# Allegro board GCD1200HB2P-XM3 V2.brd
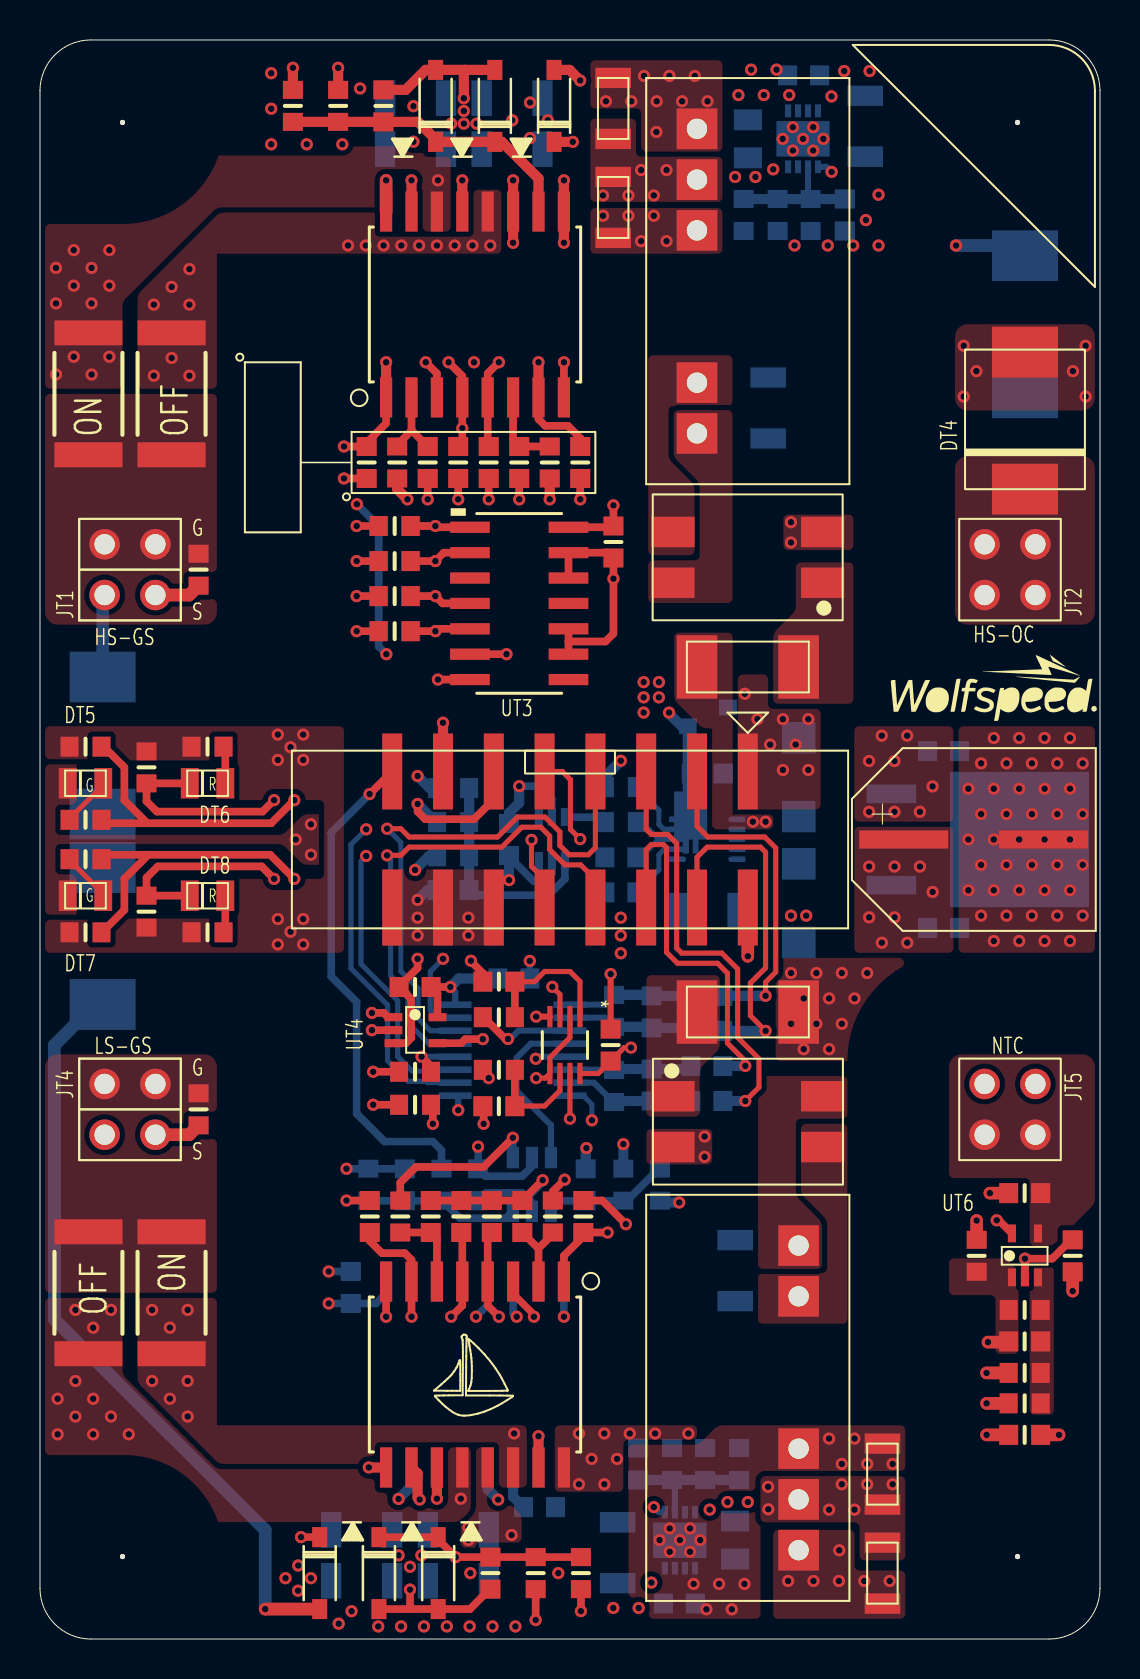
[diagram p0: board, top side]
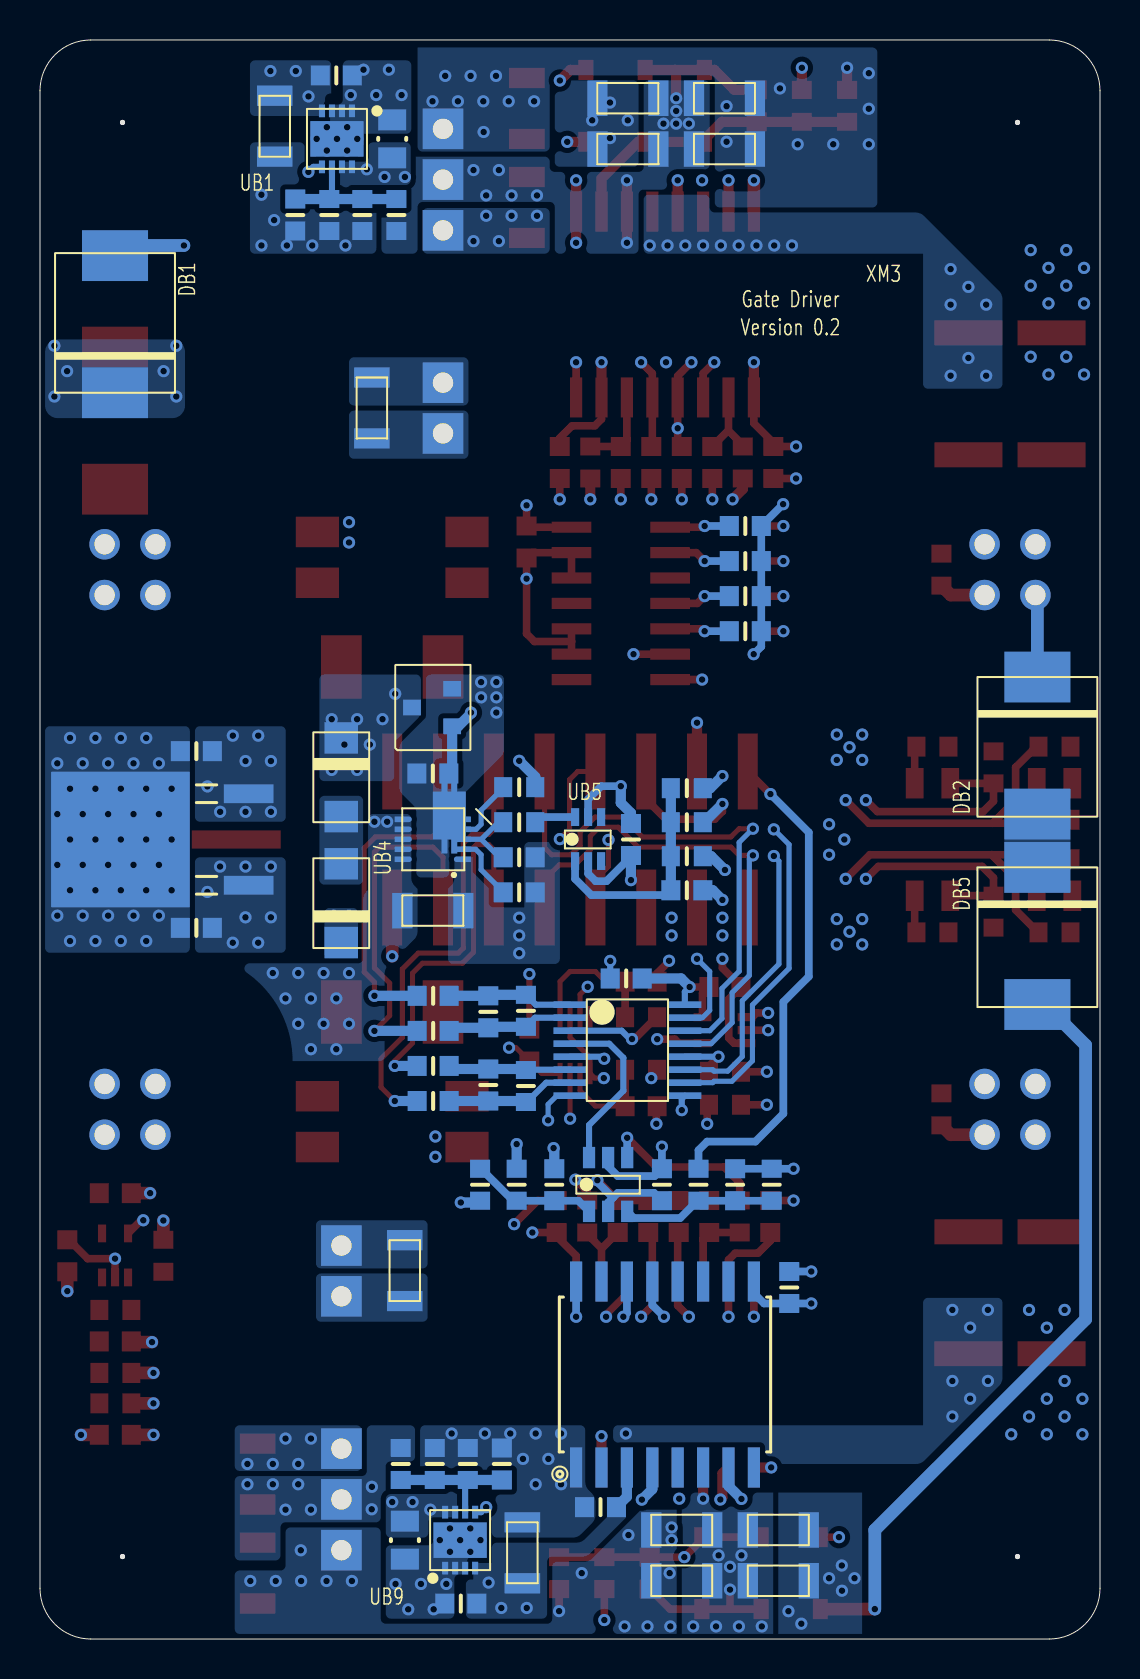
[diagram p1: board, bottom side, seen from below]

Outline 53 x 80 mm; copper layers: TOP, LAYER2, LAYER3, LAYER4, LAYER5, BOTTOM. Coordinates in mm from the lower left corner of the outline.
Outline path: 0,77.46 arc(0.74,79.26) 2.54,80 50.46,80 arc(52.26,79.26) 53,77.46 53,2.54 arc(52.26,0.74) 50.46,0 2.54,0 arc(0.74,0.74) 0,2.54 0,77.46

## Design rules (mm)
constraint set DEFAULT: min track width 0.254
net group FAULT: nets FAULT-OUTPUT-N FAULT-OUTPUT-P
net group HS-PWM: nets HS-PWM-N HS-PWM-P
net group LS-PWM: nets LS-PWM-N LS-PWM-P
net group RTD-OUTPUT: nets RTD-OUTPUT-N RTD-OUTPUT-P
net group HIGH_SIDE: nets HS-GATE N5948959 N6026555 N6026735 N6026739
net group HS_TO_VDC_DESAT_MIDPOINT: nets N6026743
net group LOW_SIDE: nets LS-GATE N5110224 N5949233 N6009828 N6009832 RTD1 RTD-ISO
net group PRIMARY: nets FAULT FLT_HS FLT_LS HS-PWM HS-PWM-INPUT LOGIC-ENABLE LS-PWM LS-PWM-INPUT N5110410 N5776744 N5776884 N5776892 N5776900 N5786131 N5786223 N5786329 N5786365 N5786573 N5786769 N5791884 N5791888 N5813663 N5829702 N5829738 N5829966 N5871306 N5927082 N5941912 N5941952 N6007380 N6007384 N6024502 N6026359 N6026535 N6032095 PS-DIS RDY_HS RDY_LS RESET RESET INPUT RTD-NON-ISO

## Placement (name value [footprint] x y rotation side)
CB1  2.2uF  [CAPC1608X90N]  38.18 78.23 180 bottom
CB2  10uF  [C_1206]  23.6 77.08 0 bottom
CB3  10uF  [C_1206]  18.78 77.08 0 bottom
CB4  10uF  [C_1206]  41.26 75.69 90 bottom
CB5  10uF  [C_1206]  23.6 74.54 0 bottom
CB6  10uF  [C_1206]  18.78 74.54 0 bottom
CB7  10000pF  [CAPC1608X90N]  40.24 71.24 90 bottom
CB8  10uF  [C_1206]  36.41 61.59 90 bottom
CB9  56 pF  [CAPC1608X90N]  17.74 55.68 180 bottom
CB10  56 pF  [CAPC1608X90N]  17.74 53.93 180 bottom
CB11  56 pF  [CAPC1608X90N]  17.74 52.18 180 bottom
CB12  56 pF  [CAPC1608X90N]  17.74 50.42 180 bottom
CB13  2.2uF  [CAPC1608X90N]  45.18 44.42 180 bottom
CB14  2.2uF  [CAPC1608X90N]  33.36 43.3 0 bottom
CB15  2.2uF  [CAPC1608X90N]  23.45 40 270 bottom
CB16  56 pF  [CAPC1608X90N]  29.04 39.11 180 bottom
CB17  10000pF  [CAPC1608X90N]  20.66 37.46 180 bottom
CB18  56 pF  [CAPC1608X90N]  29.04 37.36 180 bottom
CB19  10uF  [C_1206]  33.36 36.44 180 bottom
CB20  2.2uF  [CAPC1608X90N]  45.18 35.58 180 bottom
CB21  2.2uF  [CAPC1608X90N]  23.69 33.05 0 bottom
CB22  56 pF  [CAPC1608X90N]  30.59 31.38 90 bottom
CB23  56 pF  [CAPC1608X90N]  30.59 27.72 270 bottom
CB24  10000pF  [CAPC1608X90N]  27.29 22.73 90 bottom
CB25  2.2uF  [CAPC1608X90N]  21.9 22.73 270 bottom
CB26  56 pF  [CAPC1608X90N]  18.24 22.73 90 bottom
CB27  10uF  [C_1206]  34.76 18.43 270 bottom
CB28  2.2uF  [CAPC1608X90N]  15.54 17.59 90 bottom
CB29  10000pF  [CAPC1608X90N]  29.91 8.76 270 bottom
CB30  2.2uF  [CAPC1608X90N]  24.98 6.6 180 bottom
CB31  10uF  [C_1206]  20.91 5.46 180 bottom
CB32  10uF  [C_1206]  16.09 5.46 180 bottom
CB33  10uF  [C_1206]  28.88 4.31 270 bottom
CB34  10uF  [C_1206]  20.91 2.92 180 bottom
CB35  10uF  [C_1206]  16.09 2.92 180 bottom
CB36  2.2uF  [CAPC1608X90N]  31.96 1.77 0 bottom
CT1  56 pF  [CAPC1608X90N]  17.17 76.7 90 top
CT2  10uF  [C_1206]  28.66 76.58 270 top
CT3  10uF  [C_1206]  28.66 71.62 270 top
CT4  2.2uF  [CAPC1608X90N]  16.33 58.86 90 top
CT5  56 pF  [CAPC1608X90N]  19.38 58.86 270 top
CT6  56 pF  [CAPC1608X90N]  20.91 58.86 270 top
CT7  56 pF  [CAPC1608X90N]  22.44 58.86 270 top
CT8  56 pF  [CAPC1608X90N]  23.96 58.86 270 top
CT9  2.2uF  [CAPC1608X90N]  27.01 58.86 270 top
CT10  2.2uF  [CAPC1608X90N]  28.67 54.88 270 top
CT11  100uF  [ALUMELEC_8MMX10_5MM]  46.69 40 0 top
CT12  56 pF  [CAPC1608X90N]  22.94 32.89 180 top
CT13  2.2uF  [CAPC1608X90N]  18.75 32.62 180 top
CT14  2.2uF  [CAPC1608X90N]  28.53 29.72 90 top
CT15  56 pF  [CAPC1608X90N]  22.94 26.66 180 top
CT16  10000pF  [CAPC1608X90N]  49.23 22.31 180 top
CT17  2.2uF  [CAPC1608X90N]  16.49 21.14 90 top
CT18  56 pF  [CAPC1608X90N]  19.54 21.14 90 top
CT19  56 pF  [CAPC1608X90N]  21.06 21.14 90 top
CT20  56 pF  [CAPC1608X90N]  22.59 21.14 90 top
CT21  56 pF  [CAPC1608X90N]  24.12 21.14 90 top
CT22  2.2uF  [CAPC1608X90N]  27.17 21.14 270 top
CT23  2.2uF  [CAPC1608X90N]  51.63 19.17 270 top
CT24  56 pF  [CAPC1608X90N]  49.23 14.89 180 top
CT25  2.2uF  [CAPC1608X90N]  49.23 10.21 180 top
CT26  10uF  [C_1206]  42.12 8.25 90 top
CT27  56 pF  [CAPC1608X90N]  22.52 3.3 270 top
CT28  10uF  [C_1206]  42.12 3.3 90 top
DB1  US3M-13  [DO-214AB-SMC]  49.25 62.35 90 bottom
DB2  US3M-13  [DO-214AB-SMC]  3.13 48.13 270 bottom
DB3  SMAJ5932B-TP  [DO-214AC]  37.94 43.11 90 bottom
DB4  STPS2150A  [DO-214AC]  37.94 36.81 270 bottom
DB5  US3M-13  [DO-214AB-SMC]  3.13 38.6 270 bottom
DT1  BAT42W-TP  [SOD123]  19.78 76.7 90 top
DT2  10 V  [SOD123]  22.74 76.7 90 top
DT3  5.1 V  [SOD123]  25.71 76.7 90 top
DT4  US3M-13  [DO-214AB-SMC]  49.25 57.53 90 top
DT5  LG R971-KN-1  [D_0805]  2.27 42.82 180 top
DT6  LH R974-LP-1  [D_0805]  8.38 42.82 180 top
DT7  LG R971-KN-1  [D_0805]  2.27 37.18 180 top
DT8  LH R974-LP-1  [D_0805]  8.38 37.18 180 top
DT9  5.1 V  [SOD123]  13.99 3.3 270 top
DT10  10 V  [SOD123]  16.95 3.3 270 top
DT11  BAT42W-TP  [SOD123]  19.91 3.3 270 top
FT1  750 mA  [FUSE_SMD_SSQ2410]  35.39 48.63 0 top
FT2  750 mA  [FUSE_SMD_SSQ2410]  35.39 31.37 180 top
JT1  ESQ-102-33-L-D  [CON_2X2_100MIL_TH]  3.23 54.77 0 top
JT2  ESQ-102-33-L-D  [CON_2X2_100MIL_TH]  47.23 54.77 0 top
JT3  CON 2x8 SM  [CON_2X8_SHROUDED_SM]  26.5 40 270 top
JT4  ESQ-102-33-L-D  [CON_2X2_100MIL_TH]  3.23 27.77 0 top
JT5  ESQ-102-33-L-D  [CON_2X2_100MIL_TH]  47.23 27.77 0 top
LB1  1 uH  [INDC1608X95N]  33.34 32.18 180 bottom
LB2  1 uH  [INDC1608X95N]  33.34 30.43 180 bottom
LB3  1 uH  [INDC1608X95N]  33.34 28.67 180 bottom
LB4  1 uH  [INDC1608X95N]  33.34 26.92 180 bottom
LT1  10uH  [SRF0905]  35.38 54.12 180 top
LT2  10uH  [SRF0905]  35.4 25.88 0 top
NOREF  -  []  6.77 0 90 top
NOREF#2  -  []  48.88 4.12 90 top
NOREF#3  -  []  49.23 46.6 0 top
NOREF#4  -  []  51.69 2.05 0 top
NOREF#5  -  [unnamed#2]  4.12 4.12 0 top
NOREF#6  -  [unnamed#2]  48.88 75.88 0 top
NOREF#7  -  [unnamed#2]  48.88 4.12 0 top
NOREF#8  -  []  19.47 10.99 0 top
NOREF#9  -  []  4.12 4.12 0 top
NOREF#10  -  []  0 71.68 0 top
NOREF#11  -  [unnamed#2]  4.12 75.88 0 top
RB1  0  [RESC2012X70N]  35.39 75.05 270 bottom
RB2  10k  [RESC1608X55N]  38.54 71.24 90 bottom
RB3  10k  [RESC1608X55N]  36.88 71.24 90 bottom
RB4  2.2k  [RESC1608X55N]  35.18 71.24 90 bottom
RB5  120  [RESC1608X55N]  29.04 42.62 0 bottom
RB6  10k  [RESC1608X55N]  20.66 42.57 180 bottom
RB7  120  [RESC1608X55N]  29.04 40.87 180 bottom
RB8  120  [RESC1608X55N]  20.66 40.87 180 bottom
RB9  10k  [RESC1608X55N]  20.66 39.16 0 bottom
RB10  120  [RESC1608X55N]  28.7 31.43 270 bottom
RB11  120  [RESC1608X55N]  28.7 27.67 90 bottom
RB12  10k  [RESC1608X55N]  31 22.73 270 bottom
RB13  120  [RESC1608X55N]  29.17 22.73 90 bottom
RB14  120  [RESC1608X55N]  20.07 22.73 90 bottom
RB15  10k  [RESC1608X55N]  16.41 22.73 270 bottom
RB16  2.2k  [RESC1608X55N]  34.96 8.76 270 bottom
RB17  10k  [RESC1608X55N]  33.26 8.76 270 bottom
RB18  10k  [RESC1608X55N]  31.61 8.76 270 bottom
RB19  0  [RESC2012X70N]  34.76 4.95 90 bottom
RT1  2.2k  [RESC1608X55N]  12.64 76.7 90 top
RT2  120  [RESC1608X55N]  14.91 76.7 90 top
RT3  1  [RESC6432X70N]  2.42 62.3 270 top
RT4  1  [RESC6432X70N]  6.58 62.3 270 top
RT5  120  [RESC1608X55N]  17.86 58.86 90 top
RT6  120  [RESC1608X55N]  25.49 58.86 90 top
RT7  120  [RESC1608X55N]  17.74 55.68 0 top
RT8  120  [RESC1608X55N]  17.74 53.93 0 top
RT9  10k  [RESC1608X55N]  7.93 53.5 270 top
RT10  120  [RESC1608X55N]  17.74 52.18 0 top
RT11  120  [RESC1608X55N]  17.74 50.42 0 top
RT12  120  [RESC1608X55N]  2.27 44.64 180 top
RT13  330  [RESC1608X55N]  8.38 44.64 180 top
RT14  10k  [RESC1608X55N]  5.33 43.61 270 top
RT15  330  [RESC1608X55N]  2.27 40.99 0 top
RT16  330  [RESC1608X55N]  2.27 39.01 0 top
RT17  10k  [RESC1608X55N]  5.33 36.39 90 top
RT18  120  [RESC1608X55N]  2.27 35.36 180 top
RT19  330  [RESC1608X55N]  8.38 35.36 180 top
RT20  120  [RESC1608X55N]  22.94 31.11 0 top
RT21  120  [RESC1608X55N]  22.94 28.48 0 top
RT22  10k  [RESC1608X55N]  18.75 28.38 0 top
RT23  10k  [RESC1608X55N]  18.75 26.73 0 top
RT24  10k  [RESC1608X55N]  7.93 26.5 270 top
RT25  120  [RESC1608X55N]  18.01 21.14 270 top
RT26  120  [RESC1608X55N]  25.64 21.14 270 top
RT27  2.2k  [RESC1608X55N]  46.83 19.17 90 top
RT28  1  [RESC6432X70N]  2.42 17.32 90 top
RT29  1  [RESC6432X70N]  6.58 17.32 90 top
RT30  10k  [RESC1608X55N]  49.23 16.46 180 top
RT31  10k  [RESC1608X55N]  49.23 13.31 180 top
RT32  10k  [RESC1608X55N]  49.23 11.79 0 top
RT33  120  [RESC1608X55N]  24.78 3.3 270 top
RT34  2.2k  [RESC1608X55N]  27.05 3.3 270 top
UB1  LT3015EDD#TRPBF  [8-WDFN_EXPOSED_PAD]  38.15 75.05 270 bottom
UB2  DMP3056L-7  [SOT_23_3]  35.26 48.99 270 bottom
UB3  MC7805BDTG  [DPAK-3]  48.98 40 90 bottom
UB4  MP5000ADQ-LF-P  [10-VFDFN-THERMAL-V3_NO_VIA]  32.31 39.01 0 bottom
UB5  NC7WZ16P6X  [SC70_6]  26.25 38.92 180 bottom
UB6  2/2  [TSSOP_16]  23.63 29.46 180 bottom
UB7  SN74LVC2G14DBVR  [SOT_23_6]  25.55 21.39 180 bottom
UB8  ISO7810DWR  [DW0016B_N]  21.75 13.23 90 bottom
UB9  LT3015EDD#TRPBF  [8-WDFN_EXPOSED_PAD]  31.99 4.95 90 bottom
UT1  MGJ2D121505SC  [MGJ2]  32.85 60.31 90 top
UT2  ADUM4135  [DW0016B_N]  21.75 66.77 90 top
UT3  AND_4_2x  [D14]  23.96 51.81 0 top
UT4  SN74LVC1G32DCKR  [SC70_5]  17.67 31.11 270 top
UT5  XOR2 2X  [US8_2P40X2P10]  26.25 29.72 270 top
UT6  TLV7011DCKT  [SC70_5]  48.6 18.09 0 top
UT7  ADUM4135  [DW0016B_N]  21.75 13.23 270 top
UT8  MGJ2D121505SC  [MGJ2]  37.93 19.69 270 top

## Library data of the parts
CB1-CB36 CT1-CT10 CT12-CT28 = CAP
CT11 = CAP_P
DB1 DB2 DB5 DT4 = DIODE_1
DB3 DT2 DT10 = DIODE_ZENER_3
DB4 = DIODE_SCHOTTKY_13
DT1 DT11 = DIODE_SCHOTTKY_11
DT3 DT9 = DIODE_ZENER_4
DT5-DT8 = LED
FT1 FT2 = FUSE
JT1 JT2 JT4 JT5 = CON_2x2_100mil
JT3 = CON16A_Corrected
LB1-LB4 = INDUCTOR
LT1 LT2 = CM choke - LPD3015_2
RB1-RB19 RT1-RT34 = RES
UB1 UB9 = LT3015
UB2 = MOSFET_P_GSD
UB3 = MC7805BDTG: User Part Number: TMP-1562; Tolerance: TOL
UB4 = MP5000A_5
UB5 = BUFFER_2X_6P
UB6 = SN65C1167
UB7 = SN74LVC2G04
UB8 = ISO7810DWR: User Part Number: TMP-1565; Tolerance: TOL
UT1 UT8 = MGJ2
UT2 UT7 = ADUM4135BRWZ: User Part Number: TMP-1586; Tolerance: TOL
UT3 = AND4_2X: User Part Number: TMP-1541; Tolerance: TOL
UT4 = SN74LVC1G32
UT5 = XOR2_2X: User Part Number: TMP-1551; Tolerance: TOL
UT6 = TLV7011DCKT

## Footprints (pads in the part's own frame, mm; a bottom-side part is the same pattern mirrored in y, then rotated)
8-WDFN_EXPOSED_PAD
  rect 0.635x0.305 smd: 1(-1.4,0.75) 2(-1.4,0.25) 3(-1.4,-0.25) 4(-1.4,-0.75) 5(1.4,-0.75) 6(1.4,-0.25) 7(1.4,0.25) 8(1.4,0.75)
  rect 1.778x2.667 smd: 9(0,0)
10-VFDFN-THERMAL-V3_NO_VIA
  custom 0.07x0.07 smd: 1(-0.43,0) 2(-0.43,-0.5) 3(-0.43,-1) 4(-0.43,-1.5) 5(-0.43,-2) 6(2.53,-2) 7(2.53,-1.5) 8(2.53,-1) 9(2.53,-0.5) 10(2.53,0)
  custom 0.412x0.412 smd: 11(0.225,-2.19)
ALUMELEC_8MMX10_5MM
  rect 4.445x0.914 smd: 1(-3.505,0) 2(3.48,0)
C_1206
  rect 1.016x1.778 smd: 1(-1.524,0) 2(1.524,0)
CAPC1608X90N
  rect 0.95x1 smd: 1(-0.8,0) 2(0.8,0)
CON_2X2_100MIL_TH
  round 1.524 hole 1.016: 1(0,0) 2(0,-2.54) 3(2.54,0) 4(2.54,-2.54)
CON_2X8_SHROUDED_SM
  rect 3.8x1 smd: 1(-3.404,8.89) 2(3.404,8.89) 3(-3.404,6.35) 4(3.404,6.35) 5(-3.404,3.81) 6(3.404,3.81) 7(-3.404,1.27) 8(3.404,1.27) 9(-3.404,-1.27) 10(3.404,-1.27) 11(-3.404,-3.81) 12(3.404,-3.81) 13(-3.404,-6.35) 14(3.404,-6.35) 15(-3.404,-8.89) 16(3.404,-8.89)
D14
  rect 1.981x0.559 smd: 1(-2.464,3.81) 2(-2.464,2.54) 3(-2.464,1.27) 4(-2.464,0) 5(-2.464,-1.27) 6(-2.464,-2.54) 7(-2.464,-3.81) 8(2.464,-3.81) 9(2.464,-2.54) 10(2.464,-1.27) 11(2.464,0) 12(2.464,1.27) 13(2.464,2.54) 14(2.464,3.81)
D_0805
  rect 0.889x1.524 smd: 1(-0.889,0) 2(0.889,0)
DO-214AB-SMC
  rect 2.54x3.302 smd: A(6.858,0) C(0,0)
DO-214AC
  rect 1.575x1.676 smd: A(-1.968,0) C(1.968,0)
DPAK-3
  rect 0.94x2.489 smd: 1(-2.29,-6.413) 3(2.29,-6.413)
  rect 6.782x6.934 smd: 2(0,0)
DW0016B_N
  rect 2.007x0.61 smd: 1(-4.65,4.445) 2(-4.65,3.175) 3(-4.65,1.905) 4(-4.65,0.635) 5(-4.65,-0.635) 6(-4.65,-1.905) 7(-4.65,-3.175) 8(-4.65,-4.445) 9(4.65,-4.445) 10(4.65,-3.175) 11(4.65,-1.905) 12(4.65,-0.635) 13(4.65,0.635) 14(4.65,1.905) 15(4.65,3.175) 16(4.65,4.445)
FUSE_SMD_SSQ2410
  rect 2.032x3.175 smd: 1(-2.54,0) 2(2.54,0)
INDC1608X95N
  rect 0.95x1 smd: 1(-0.8,0) 2(0.8,0)
MGJ2
  rect 2.032x2.032 hole 1.016: 1(0,0) 2(2.54,0) 5(10.16,0) 6(12.7,0) 7(15.24,0)
RESC1608X55N
  rect 0.9x1 smd: 1(-0.8,0) 2(0.8,0)
RESC2012X70N
  rect 1.05x1.4 smd: 1(-0.95,0) 2(0.95,0)
RESC6432X70N
  rect 1.25x3.4 smd: 1(-3.05,0) 2(3.05,0)
SC70_5
  rect 0.406x0.889 smd: 1(0,0) 2(0.65,0) 3(1.3,0) 4(1.3,2.2) 5(0,2.2)
SC70_6
  rect 0.406x0.889 smd: 1(0,0) 2(0.65,0) 3(1.3,0) 4(1.3,2.2) 5(0.65,2.2) 6(0,2.2)
SOD123
  rect 1x0.75 smd: A(1.8,0) C(-1.8,0)
SOT_23_3
  rect 0.787x0.889 smd: 1(3.327,2.87) 2(1.448,2.87) 3(2.388,0.864)
SOT_23_6
  rect 0.61x1.067 smd: 1(0,0) 2(0.953,0) 3(1.905,0) 4(1.905,2.692) 5(0.953,2.692) 6(0,2.692)
SRF0905
  rect 2.159x1.524 smd: 1(-3.747,1.27) 2(-3.747,-1.27) 3(3.734,-1.27) 4(3.734,1.27)
TSSOP_16
  rect 1.651x0.33 smd: 1(-2.87,2.276) 2(-2.87,1.626) 3(-2.87,0.975) 4(-2.87,0.325) 5(-2.87,-0.325) 6(-2.87,-0.975) 7(-2.87,-1.626) 8(-2.87,-2.276) 9(2.87,-2.276) 10(2.87,-1.626) 11(2.87,-0.975) 12(2.87,-0.325) 13(2.87,0.325) 14(2.87,0.975) 15(2.87,1.626) 16(2.87,2.276)
unnamed#2
  round 0.254 hole 4.445 unplated: (0,0)
US8_2P40X2P10
  rect 1.067x0.254 smd: 1(-1.422,0.75) 2(-1.422,0.25) 3(-1.422,-0.25) 4(-1.422,-0.75) 5(1.422,-0.75) 6(1.422,-0.25) 7(1.422,0.25) 8(1.422,0.75)

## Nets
5V: CB13.2 CB15.1 CB21.1 CB25.1 CB28.2 CT4.1 CT9.1 CT10.1 CT13.1 CT14.1 CT17.1 CT22.1 RB9.1 RB12.2 RT12.2 RT13.2 RT14.1 RT17.1 RT18.2 RT19.2 RT22.2 RT23.2 UB3.3(OUT) UB5.5(VCC) UB6.12 UB6.16(VCC) UB7.5 UB8.14(VCC2) UT2.7 UT3.14 UT4.5 UT5.8 UT7.7
12V: CB14.2 CB20.2 CT11.1 UB2.2(S) UB3.1 UB4.11(VCC)
12V_SWITCHED: CB19.1 FT1.1 FT2.1 RB5.1 UB4.6 UB4.7 UB4.8 UB4.9 UB4.10
-5V_HS: CB1.2 CT3.2 RB1.1 UB1.1 UB1.2 UB1.3(SHDN) UB1.9 UT1.5
-5V_LS: CB36.2 CT26.2 RB19.1 UB9.1 UB9.2 UB9.3(SHDN) UB9.9 UT8.5
0: CB9.2 CB10.2 CB11.2 CB12.2 CB13.1 CB14.1 CB15.2 CB16.2 CB17.2 CB18.2 CB19.2 CB20.1 CB21.2 CB24.2 CB25.2 CB26.2 CB28.1 CT4.2 CT5.2 CT6.2 CT7.2 CT8.2 CT9.2 CT10.2 CT11.2 CT12.2 CT13.2 CT14.2 CT15.2 CT17.2 CT18.2 CT19.2 CT20.2 CT21.2 CT22.2 DB4.C DT5.2(C) DT7.2(C) JT3.2 JT3.12 JT3.14 JT3.16 LT1.2 LT2.2 RB6.2 RB15.1 UB2.1 UB3.2 UB4.1 UB5.2 UB6.8 UB7.2 UB8.9 UB8.16 UT2.1 UT2.3 UT2.8 UT3.7 UT3.9 UT3.10 UT3.12 UT3.13 UT4.3 UT5.4 UT7.1 UT7.3 UT7.8
FAULT: UB6.15 UT3.6
FAULT-OUTPUT-N: JT3.8 UB6.13
FAULT-OUTPUT-P: JT3.7 UB6.14
FLT_HS: CT7.1 DT6.2(C) RT7.1 RT14.2 UT2.5
FLT_LS: CT19.1 DT8.2(C) RT8.1 RT17.2 UT7.5
HS-DRAIN: DT4.C(CATHODE) JT2.1 JT2.2 JT2.3 JT2.4
HS-GATE: JT1.1 JT1.3 RT3.2 RT4.2 RT9.1 UT2.15
HS-PWM: RT5.1 UT5.7
HS-PWM-INPUT: RT20.1 RT23.1 UB6.3 UT4.1
HS-PWM-N: JT3.4 LB2.1
HS-PWM-P: JT3.3 LB1.1
HS-SOURCE: CB1.1 CB2.1 CB3.2 CB4.2 CB5.1 CB6.2 CT1.2 CT2.2 CT3.1 DB2.C(CATHODE) DT1.A DT2.A JT1.2 JT1.4 RB4.1 RT9.2 UB1.4 UB1.5 UT1.6(COM) UT2.11
HS-VDD: CB3.1 CB6.1 CT2.1 RT1.2 UT1.7 UT2.13
HS-VSS: CB2.2 CB4.1 CB5.2 CB7.1 RB1.2 RB2.1 RB3.1 UB1.7 UB1.8 UT2.9 UT2.16(VSS2_1)
LOGIC-ENABLE: JT3.13 RB13.2
LS-GATE: JT4.1 JT4.3 RT24.1 RT28.2 RT29.2 UT7.15
LS-PWM: RT26.1 UT5.3(Y)
LS-PWM-INPUT: RT21.1 RT22.1 UB6.5 UT4.2
LS-PWM-N: JT3.6 LB3.1
LS-PWM-P: JT3.5 LB4.1
LS-SOURCE: CB30.2 CB31.2 CB32.1 CB33.2 CB34.2 CB35.1 CB36.1 CT23.2 CT25.2 CT26.1 CT27.2 CT28.2 DT10.A DT11.A JT4.2 JT4.4 RB16.1 RT24.2 RT32.1 UB8.3 UB9.4 UB9.5 UT6.5(VCC) UT7.11 UT8.6(COM)
LS-VDD: CB31.1 CB34.1 CT28.1 RT34.2 UT7.13 UT8.7
LS-VSS: CB29.1 CB30.1 CB32.2 CB33.1 CB35.2 CT16.2 CT23.1 CT25.1 RB17.1 RB18.1 RB19.2 RT31.2 UB8.1 UB8.7 UB9.7 UB9.8 UT6.2 UT7.9 UT7.16(VSS2_1)
NC2: UT3.3
NC_1: UB8.5
NC_2: UB8.6
NC_3: UB8.8
NC_4: UB8.10
NC_5: UB8.11
NC_6: UB8.12
NC_7: UB8.15
PS-DIS: JT3.11 RB8.2
RDY_HS: CT6.1 RT10.1 RT12.1 RT15.2 UT2.4
RDY_LS: CT20.1 RT11.1 RT16.2 RT18.1 UT7.4
RESET: RT6.1 RT25.1 UB7.4(2Y)
RESET INPUT: JT3.15 RB14.2
RTD1: JT5.1 JT5.3 RT27.2
RTD2: CT16.1 JT5.2 JT5.4 UT6.4
RTD-ISO: CT24.2 RT27.1 RT30.2 UB8.4 UT6.1
RTD-NON-ISO: UB6.9 UB8.13
RTD-OUTPUT-N: JT3.10 UB6.11
RTD-OUTPUT-P: JT3.9 UB6.10
UNPROTECTED_VIN: DB3.C JT3.1 UB2.3
VOUT_OFF_HS: RT4.1 UT2.12
VOUT_OFF_LS: RT28.1 UT7.12
VOUT_ON_HS: RT3.1 UT2.14
VOUT_ON_LS: RT29.1 UT7.14
N5110224: CT27.1 DT10.C DT11.C RT33.1 RT34.1 UT7.10
N5110410: CT21.1 RT26.2 UT7.2
N5143626: FT1.2 LT1.1
N5776744: RB5.2 UB4.4
N5776884: CB18.1 UB4.2
N5776892: CB17.1 RB6.1 RB8.1 RB9.2 UB5.1
N5776900: CB16.1 RB7.1 UB4.3
N5777665: CB8.1 LT1.4 UT1.1
N5777737: CB8.2 LT1.3 UT1.2
N5778706: CB27.1 LT2.4 UT8.1
N5778794: CB27.2 LT2.3 UT8.2
N5780153: FT2.2 LT2.1
N5786131: CB22.1 LB2.2 RB10.2 UB6.2
N5786223: CB22.2 LB1.2 RB10.1 UB6.1
N5786329: CB23.1 LB3.2 RB11.2 UB6.6
N5786365: CB23.2 LB4.2 RB11.1 UB6.7
N5786573: UB6.4 UB7.6
N5786769: CB24.1 RB12.1 RB13.1 UB7.1
N5791884: DT8.1 RT19.1
N5791888: DT6.1 RT13.1
N5813663: CB9.1 RT7.2 UT3.1
N5829702: CT12.1 RT20.2 UT5.1
N5829738: UT4.4(Y) UT5.2 UT5.5
N5829966: CT15.1 RT21.2 UT5.6
N5871306: CB11.1 RT10.2 UT3.4
N5927082: DB3.A DB4.A
N5941912: CB10.1 RT8.2 UT3.2
N5941952: CB12.1 RT11.2 UT3.5
N5948959: CB7.2 RB2.2 RB3.2 RB4.2 UB1.6
N5949233: CB29.2 RB16.2 RB17.2 RB18.2 UB9.6
N5961728: CT24.1 RT30.1 RT31.1 RT32.2 UT6.3
N6007380: DT7.1 RT16.1
N6007384: DT5.1 RT15.1
N6009828: DT9.C RT33.2
N6009832: DB5.A DT9.A
N6009836: DB2.A DB5.C(CATHODE)
N6024502: CB26.1 RB14.1 RB15.2 UB7.3
N6026359: CT5.1 RT5.2 UT2.2
N6026535: CT8.1 RT6.2 UT2.6
N6026555: CT1.1 DT1.C DT2.C RT1.1 RT2.1 UT2.10
N6026735: DT3.C RT2.2
N6026739: DB1.A DT3.A
N6026743: DB1.C(CATHODE) DT4.A
N6032095: CT18.1 RT25.2 UT7.6
N57768605: RB7.2 UB5.6

Pads without a net: UB4 5; UB5 3 4; UB8 2; UT3 8 11

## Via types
v1: diameter 0.61, hole 0.33, TOP to BOTTOM, 430 vias

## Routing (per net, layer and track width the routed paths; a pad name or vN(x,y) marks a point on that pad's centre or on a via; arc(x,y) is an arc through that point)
5V: length 46.2
  TOP w0.254: v1(29.55,29.59) 29.2,29.59 CT14.1 27.91,28.29 UT5.8
  TOP w0.381: v1(28.67,56.72) CT10.1 28.61,55.62 UT3.14 ; CT9.1 27.01,60.08 26.4,60.7 25.26,60.7 24.93,61.03 UT2.7 ; v1(29.29,20.75) 28.11,21.94 CT22.1 ; v1(19.08,29.13) 19.55,28.66 RT22.2 ; RT23.2 19.64,26.64 v1(19.64,25.78) ; CT17.1 16.49,19.92 17.1,19.3 18.24,19.3 18.58,18.97 UT7.7 v1(18.58,16.12) ; UT4.5 19.87,32.3 CT13.1 v1(20.52,32.62) ; CT4.1 v1(15.2,58.06)
  TOP w0.508: v1(24.93,63.88) UT2.7
  BOTTOM w0.305: v1(20.52,32.62) 20.76,32.38 UB6.16 ; UB6.12 v1(19.08,29.13)
  BOTTOM w0.381: UB5.5 25.6,42.01 24.94,42.67 v1(23.96,42.67) ; UB8.14 23.66,16.3 v1(23.83,16.12) ; UB7.5 24.59,23.64 24.11,23.16 22.27,23.16 CB25.1 v1(21.9,24.63) ; CB28.2 v1(14.44,18.39)
  BOTTOM w0.508: RB12.2 31.09,21.84 v1(31.96,21.84) ; RB9.1 19.44,39.16 v1(18.75,38.48) ; v1(23.96,42.67) 23.96,41.83 23.45,41.33 CB15.1 ; CB21.1 20.94,33.05 v1(20.52,32.62)
  vias: v1(11.89,45.25) v1(11.89,43.98) v1(11.89,36.02) v1(11.89,34.75) v1(12.53,44.61) v1(12.53,35.39) v1(13.16,45.25) v1(13.16,43.98) v1(13.16,36.02) v1(13.16,34.75) v1(21.7,63.88) v1(41.45,43.93) v1(41.45,41.39) v1(42.09,45.2) v1(42.72,43.93) v1(42.72,41.39) v1(43.36,45.2) v1(43.99,41.39) v1(44.63,42.66)
12V:
  vias: v1(30.18,47.87) v1(30.18,47.11) v1(30.18,46.35) v1(30.95,47.87) v1(30.95,47.11) v1(41.46,38.65) v1(41.46,36.11) v1(42.09,34.84) v1(42.73,38.65) v1(42.73,36.11) v1(43.36,34.84) v1(44,38.65) v1(44.63,37.38)
12V_SWITCHED: length 10.2
  LAYER3 w0.635: v1(29.04,43.94) 32.6,43.94 v1(35.64,40.89) v1(36.28,40.89)
  BOTTOM w0.508: RB5.1 28.24,43.14 v1(29.04,43.94)
  vias: v1(37.55,33.32) v1(37.55,30.78) v1(38.19,32.05) v1(38.19,29.51) v1(38.82,33.32) v1(38.82,30.78) v1(39.46,32.05) v1(39.46,29.51) v1(40.09,33.32) v1(40.09,30.78) v1(40.73,32.05) v1(41.36,33.32)
-5V_HS:
  vias: v1(28.15,71.21) v1(29.42,71.21) v1(30.06,69.94) v1(30.69,71.21) v1(31.33,69.94) v1(34.92,77.24) v1(35.56,78.51) v1(36.19,77.24) v1(36.83,78.51) v1(37.13,75.05) v1(37.46,77.24) v1(37.64,75.64) v1(37.64,74.47) v1(38.15,75.05) v1(38.66,75.64) v1(38.66,74.47) v1(39.17,75.05)
-5V_LS:
  vias: v1(30.98,4.95) v1(31.49,5.53) v1(31.49,4.36) v1(31.99,4.95) v1(32.5,5.53) v1(32.5,4.36) v1(32.68,2.76) v1(33.01,4.95) v1(33.32,1.49) v1(33.95,2.76) v1(34.59,1.49) v1(35.22,2.76) v1(39.45,10.03) v1(40.09,8.76) v1(40.72,10.03) v1(41.36,8.76) v1(42.63,8.76)
0: length 92.2
  TOP w0.305: UT5.4 v1(24.81,31.14) ; CT14.2 v1(28.53,33.27)
  TOP w0.356: UT7.3 23.66,17.27 24.7,16.23 v1(24.7,16.12)
  TOP w0.381: UT3.9 26.42,49.91 ; 26.42,49.91 UT3.10 ; 26.42,49.91 28.28,49.91 28.67,50.3 v1(28.67,53.05) CT10.2 28.41,54.35 UT3.13 UT3.12 ; v1(21.55,33.93) 21.55,33.9 22.14,33.31 CT12.2 ; CT15.2 22.18,26.62 v1(22.18,25.78) ; UT7.8 v1(17.31,16.12) ; CT7.2 v1(22.44,57.02) ; UT2.3 19.85,63.32 v1(19.29,63.88) ; CT6.2 v1(20.91,57.02) ; UT2.8 26.2,63.87 v1(26.2,63.88) ; v1(15.2,59.66) CT4.2 16.33,59.85 17.31,60.82 UT2.1 ; UT4.3 18.3,29.81 18.56,30.07 18.56,32.01 CT13.2 17.95,32.65 18.88,33.57 v1(18.88,34.03) ; CT8.2 v1(23.96,57.02) ; CT18.2 CT19.2 CT20.2 CT21.2 v1(25.13,22.95) ; CT9.2 v1(27.01,57.02) ; v1(28.38,20.34) CT22.2 27.17,20.15 26.2,19.18 UT7.1 ; CT17.2 v1(15.32,21.94) ; UT3.7 v1(19.9,48) ; CT5.2 v1(19.38,57.02)
  TOP w0.508: v1(17.31,63.88) UT2.1
  TOP w0.635: JT3.2 v1(35.39,34.16)
  BOTTOM w0.254: UB6.8 27.16,27.18 27.59,26.75 v1(27.59,25.95)
  BOTTOM w0.305: CB21.2 v1(24.49,33.93)
  BOTTOM w0.381: v1(25.13,22.95) 25.13,22.86 24.35,22.08 24.35,22.08 ; v1(15.32,23.53) RB15.1 CB26.2 ; 24.35,22.08 24.59,21.84 UB7.2 ; 24.35,22.08 24.11,22.32 22.3,22.32 CB25.2 ; 23.45,39.14 24.68,37.91 25.22,37.91 25.59,38.29 25.59,38.92 UB5.2 ; v1(15.84,56.78) CB9.2 CB10.2 CB11.2 CB12.2 16.94,49.65 v1(17.32,49.27) ; v1(14.44,16.79) CB28.1 16.8,16.79 17.31,17.3 UT7.8 ; UT7.1 v1(26.2,16.12)
  BOTTOM w0.508: v1(18.88,36.98) 19.36,37.46 CB17.2 ; v1(18.88,43.17) 19.49,42.57 RB6.2 ; CB15.2 v1(23.45,37.97) ; CB24.2 27.29,24.53 v1(27.32,24.56) ; v1(31.45,46.35) 31.45,46.3 32.09,45.66 UB2.1 32.39,43.47 CB14.1
  vias: v1(12.78,40) v1(13.55,40.76) v1(13.55,39.24) v1(18.88,36.09) v1(18.88,35.2) v1(21.42,36.09) v1(21.42,35.2) v1(29.04,36.09) v1(29.04,35.2) v1(29.04,34.31) v1(33.23,25.14) v1(33.23,24.12) v1(37.55,55.87) v1(37.55,54.86) v1(37.55,36.19) v1(38.31,36.19) v1(46.42,42.54) v1(46.42,40) v1(46.42,37.46) v1(47.05,43.81) v1(47.05,41.27) v1(47.05,38.73) v1(47.05,36.19) v1(47.69,45.08) v1(47.69,42.54) v1(47.69,40) v1(47.69,37.46) v1(47.69,34.92) v1(48.32,43.81) v1(48.32,41.27) v1(48.32,38.73) v1(48.32,36.19) v1(48.96,45.08) v1(48.96,42.54) v1(48.96,40) v1(48.96,37.46) v1(48.96,34.92) v1(49.59,43.81) v1(49.59,41.27) v1(49.59,38.73) v1(49.59,36.19) v1(50.23,45.08) v1(50.23,42.54) v1(50.23,40) v1(50.23,37.46) v1(50.23,34.92) v1(50.86,43.81) v1(50.86,41.27) v1(50.86,38.73) v1(50.86,36.19) v1(51.5,45.08) v1(51.5,42.54) v1(51.5,40) v1(51.5,37.46) v1(51.5,34.92) v1(52.13,43.81) v1(52.13,41.27) v1(52.13,38.73) v1(52.13,36.19)
FAULT: length 29
  TOP w0.381: UT3.6 v1(23.32,49.27)
  LAYER5 w0.508: v1(20.15,34.03) 20.15,36.06 21.23,37.14 25.8,37.14 27.77,39.11 27.77,42.16 23.32,46.6 v1(23.32,49.27)
  BOTTOM w0.254: v1(20.15,34.03) 19.52,33.4 19.52,31.45 19.88,31.08 UB6.15
FAULT-OUTPUT-N: length 25.5
  TOP w0.254: JT3.8 27.77,38 27.04,38.73 26.25,38.73 25.48,39.49 25.48,40.17 25.04,40.61 24.09,40.61 23.09,39.62 18.45,39.62 18.04,39.21 v1(17.36,39.21)
  BOTTOM w0.254: v1(17.36,39.21) 17.53,39.03 17.53,33.2 18.39,32.34 18.39,30.83 19.44,29.78 UB6.13
FAULT-OUTPUT-P: length 28.4
  TOP w0.254: v1(17.36,40.54) 18.04,40.54 18.45,40.13 22.88,40.13 23.88,41.12 25.25,41.12 25.99,40.38 25.99,39.7 26.46,39.24 27.42,39.24 27.77,39.59 JT3.7
  BOTTOM w0.254: v1(17.36,40.54) 18.04,39.85 18.04,33.41 18.9,32.55 18.9,31.04 19.51,30.43 UB6.14
FLT_HS: length 43.5
  TOP w0.381: DT6.2 7.48,42.81 RT14.2 5.33,41.91 5.84,41.4 11.13,41.4 v1(11.7,41.97) ; CT7.1 22.39,59.71 UT2.5 22.39,63.32 v1(22.94,63.88) ; RT7.1 v1(15.83,55.68)
  LAYER3 w0.381: v1(11.7,41.97) 12.4,42.67 14.37,42.67 15.5,43.8 15.5,49.09 15.07,49.52 15.07,54.92 v1(15.83,55.68) 16.59,56.45 16.59,57.53 v1(22.94,63.88)
FLT_LS: length 62.2
  TOP w0.381: v1(20.56,16.12) 21.12,16.68 UT7.5 21.12,20.29 CT19.1 ; v1(11.7,38.03) 11.08,38.65 5.89,38.65 5.33,38.09 RT17.2 7.48,37.19 DT8.2 ; RT8.1 v1(15.83,53.93)
  LAYER3 w0.381: v1(20.56,16.12) 20.56,20.77 14.61,26.71 14.61,35.63 12.92,37.32 12.42,37.32 v1(11.7,38.03)
  LAYER5 w0.381: v1(11.7,38.03) 12.4,37.33 13.86,37.33 15.15,38.62 15.15,42.55 16.42,43.82 16.42,49.86 16.98,50.41 16.98,52.79 v1(15.83,53.93)
HS-GATE: length 31.6
  TOP w0.508: v1(18.58,72.98) UT2.15
  LAYER3 w0.635: JT1.1 JT1.3 8.34,57.34 8.34,69.59 9.36,70.61 16.2,70.61 v1(18.58,72.98)
HS-PWM: length 37.9
  TOP w0.254: UT5.7 v1(26.5,26.03)
  TOP w0.508: RT5.1 17.86,57.53 v1(18.37,57.02)
  LAYER3 w0.635: v1(18.37,57.02) 18.37,45.33 20.02,43.68 20.02,40 26.5,33.53 v1(26.5,26.03)
HS-PWM-INPUT: length 20.1
  TOP w0.381: UT4.1 17.39,31.11 17.18,31.32 v1(16.59,31.32) ; RT20.1 22.18,31.11 23.27,30.02 v1(23.4,30.02) ; RT23.1 v1(16.66,26.73)
  LAYER3 w0.381: v1(16.59,31.32) 16.45,31.32 15.88,30.75 15.88,27.5 v1(16.66,26.73)
  LAYER3 w0.635: v1(16.59,31.32) 22.1,31.32 v1(23.4,30.02)
  BOTTOM w0.305: v1(23.4,30.02) 23.5,30.02 23.92,30.43 UB6.3
HS-PWM-N: length 18
  TOP w0.254: v1(36.28,30.43) 35.52,31.19 35.52,32.82 36.28,33.58 36.28,39.36 36.02,39.62 33.36,39.62 32.85,39.11 JT3.4
  BOTTOM w0.508: LB2.1 v1(36.28,30.43)
HS-PWM-P: length 16.9
  TOP w0.254: JT3.3 32.85,40.67 33.39,40.13 36.24,40.13 36.79,39.58 36.79,33.37 36.28,32.86 v1(36.28,32.18)
  BOTTOM w0.508: LB1.1 v1(36.28,32.18)
HS-SOURCE: length 17.8
  TOP w0.508: v1(23.66,69.85) UT2.11 v1(23.66,72.98) ; CT1.2 18.28,77.5 19.28,78.5 DT1.A 21.26,78.5 ; 21.26,78.5 21.19,78.43 v1(21.19,77.08) ; 21.26,78.5 DT2.A
  TOP w0.635: RT9.2 7.46,52.23 JT1.4
  BOTTOM w0.305: v1(39.58,73.4) 39.33,73.65 UB1.5
  BOTTOM w0.635: JT1.2 3.13,52.13 DB2.C
  vias: v1(20.56,75.81) v1(21.19,76.45) v1(21.19,75.81) v1(21.83,75.81) v1(28.15,72.22) v1(29.42,72.22) v1(30.06,73.49) v1(30.69,72.22) v1(31.33,73.49) v1(39.58,77.18) v1(40.21,78.45) v1(41.48,78.45)
HS-VDD: length 2.7
  TOP w0.508: UT2.13 v1(21.12,72.98) ; RT1.2 v1(12.64,78.61)
  vias: v1(11.56,78.34) v1(11.56,76.56) v1(11.56,74.78) v1(13.34,74.78) v1(15.12,74.78) v1(16,77.58) v1(18.67,76.69) v1(18.67,74.91) v1(28.3,76.93) v1(29.57,76.93) v1(30.2,78.2) v1(30.84,76.93) v1(30.82,75.4) v1(31.47,78.2) v1(32.11,76.93) v1(32.74,78.2) v1(33.38,76.93)
HS-VSS: length 4.7
  TOP w0.508: v1(26.2,69.85) UT2.9 v1(26.2,72.98)
  TOP w0.635: UT2.16 v1(17.31,72.98)
  vias: v1(23.61,75.98) v1(24.5,76.87) v1(24.5,75.09) v1(25.39,75.98) v1(34.76,73.15) v1(35.77,73.15) v1(36.66,73.53) v1(37.73,69.72) v1(39.39,69.72) v1(40.66,69.72) v1(41.29,70.99) v1(41.93,72.26) v1(41.93,69.72)
LOGIC-ENABLE: length 28.5
  TOP w0.508: v1(20.15,45.84) JT3.13
  LAYER3 w0.508: v1(20.15,45.84) 21.55,44.44 21.55,41.52 27.39,35.68 27.39,28.57 29.17,26.79 v1(29.17,24.76)
  BOTTOM w0.508: RB13.2 v1(29.17,24.76)
LS-GATE: length 39.7
  TOP w0.508: UT7.15 v1(24.93,10.15)
  LAYER3 w0.635: JT4.1 JT4.3 8.47,25.07 8.47,10.54 9.1,9.9 22.44,9.9 22.94,9.39 24.17,9.39 v1(24.93,10.15)
LS-PWM: length 12.8
  TOP w0.254: UT5.3 26,32.25 v1(25.62,32.63)
  TOP w0.381: v1(26.23,22.98) 25.64,22.39 RT26.1
  LAYER3 w0.508: v1(25.62,32.63) 25.62,23.6 v1(26.23,22.98)
LS-PWM-INPUT: length 15.4
  TOP w0.381: v1(22.44,28.06) 22.14,28.35 RT21.1 ; RT22.1 v1(16.66,28.38) ; UT4.2 v1(16.59,30.46)
  LAYER3 w0.635: v1(24.79,29.03) 23.4,29.03 v1(22.44,28.06) 18.24,28.06 17.93,28.38 v1(16.66,28.38) 16.66,30.4 v1(16.59,30.46)
  BOTTOM w0.305: UB6.5 24.89,29.13 v1(24.79,29.03)
LS-PWM-N: length 18.9
  TOP w0.254: JT3.6 30.31,39.49 30.56,39.75 31.18,39.75 31.33,39.6 31.33,34.36 31.88,33.81 33.88,33.81 34.37,33.31 34.37,29.81 35.26,28.92 v1(35.26,28.67)
  BOTTOM w0.508: LB3.1 v1(35.26,28.67)
LS-PWM-P: length 21.9
  TOP w0.254: JT3.5 30.31,40.51 30.56,40.25 31.39,40.25 31.83,39.81 31.83,34.57 32.09,34.32 34.09,34.32 34.88,33.52 34.88,30.09 35.95,29.03 35.95,27.6 v1(35.26,26.92)
  BOTTOM w0.508: LB4.1 v1(35.26,26.92)
LS-SOURCE: length 17.9
  TOP w0.381: v1(18.5,2.47) 18.5,1.5 ; 18.5,1.5 DT10.A ; 18.5,1.5 DT11.A 21.5,1.5 22.5,2.5 CT27.2 ; UT6.5 47.94,20.95 v1(47.84,20.95)
  TOP w0.508: UT7.11 v1(19.85,7.02)
  TOP w0.635: CT23.2 v1(51.63,17.41) ; CT25.2 v1(47.33,10.21) ; RT24.2 7.46,25.23 JT4.4 ; RT32.1 v1(47.33,11.79)
  BOTTOM w0.305: v1(30.69,6.6) 30.94,6.35 UB9.5
  BOTTOM w0.508: UB8.3 23.66,7.12 CB30.2
  vias: v1(16.91,0.63) v1(17.93,4.19) v1(18.05,0.63) v1(18.5,3.61) v1(19.07,4.19) v1(19.2,0.63) v1(20.34,0.63) v1(28.66,1.55) v1(29.93,1.55) v1(30.57,2.82) v1(36.41,7.61) v1(36.42,6.49) v1(39.45,6.47) v1(40.09,7.74) v1(40.72,6.47) v1(41.36,7.74) v1(42.63,7.74)
LS-VDD: length 1.1
  TOP w0.381: RT34.2 v1(27.05,1.4)
  vias: v1(21.42,5.58) v1(21.42,4.95) v1(21.52,3.3) v1(21.48,0.63) v1(22.63,0.63) v1(23.58,5.2) v1(23.77,0.63) v1(25.91,3.3) v1(37.4,2.9) v1(38.67,2.9) v1(39.94,2.9) v1(39.96,4.44) v1(41.21,2.9) v1(42.48,2.9)
LS-VSS: length 9.4
  TOP w0.381: CT23.1 51.56,19.97 50.62,19.03 v1(49.25,19.03) UT6.2
  TOP w0.508: UT7.9 v1(16.44,8.58)
  TOP w0.635: CT16.2 v1(47.49,22.31) ; RT31.2 v1(47.33,13.31) ; CT25.1 v1(50.95,10.21)
  BOTTOM w0.508: v1(17.93,7.01) 18.58,7.66 UB8.7
  vias: v1(12.28,3.04) v1(12.91,3.68) v1(12.9,2.42) v1(13.55,3.04) v1(14.93,0.77) v1(15.58,1.39) v1(26.95,10.28) v1(26.95,7.74) v1(27.58,9.01) v1(28.22,10.28) v1(28.22,7.74) v1(28.85,9.01) v1(29.49,10.28) v1(30.76,10.28) v1(32.42,10.28) v1(33.48,6.47) v1(34.37,6.85) v1(35.39,6.85)
PS-DIS: length 7.5
  TOP w0.381: v1(18.88,41.78) 18.88,41.4 19.26,41.02 21.7,41.02 22.69,42 JT3.11
  BOTTOM w0.508: RB8.2 19.79,40.87 v1(18.88,41.78)
RDY_HS: length 44.9
  TOP w0.381: 5.37,40.81 11.56,40.81 v1(12.72,41.97) ; 5.37,40.81 3.25,40.81 RT15.2 ; 5.37,40.81 4.22,41.96 4.22,43.61 3.19,44.64 RT12.1 ; CT6.1 21.12,59.87 v1(21.12,60.57) UT2.4 21.12,63.19 v1(20.43,63.88) ; RT10.1 v1(15.83,52.18)
  LAYER3 w0.381: 16.62,52.19 16.6,52.18 v1(15.83,52.18) ; 16.62,52.19 16.62,55.64 17.18,56.2 17.18,57.09 18.88,58.8 19.34,58.8 v1(21.12,60.57) ; 16.62,52.19 16.62,44.09 14.5,41.97 v1(12.72,41.97)
RDY_LS: length 61.6
  TOP w0.381: 5.42,39.24 11.51,39.24 v1(12.72,38.03) ; 5.42,39.24 4.22,38.04 4.22,36.48 3.1,35.36 RT18.1 ; 5.42,39.24 3.3,39.24 RT16.2 ; CT20.1 22.39,20.13 UT7.4 22.39,16.68 v1(22.94,16.12) ; RT11.1 v1(15.83,50.42)
  LAYER3 w0.381: v1(12.72,38.03) 13.46,38.03 15.2,36.3 15.2,26.95 22.94,19.21 v1(22.94,16.12)
  LAYER5 w0.381: v1(15.83,50.42) 15.83,44.06 14.56,42.79 14.56,38.86 13.74,38.03 v1(12.72,38.03)
RESET: length 44.7
  TOP w0.381: RT25.1 18.01,22.83 18.8,23.62 22.18,23.62 v1(23.64,25.08)
  TOP w0.508: v1(25.49,57.02) RT6.1
  LAYER5 w0.508: v1(23.64,25.08) 27.26,28.7 27.26,37.59 28.41,38.73 28.41,38.74 28.48,38.82 28.48,42.45 28.41,42.53 28.41,42.54 25.49,45.46 v1(25.49,57.02)
  BOTTOM w0.381: UB7.4 v1(23.64,25.08)
RESET INPUT: length 24.8
  TOP w0.381: v1(16.48,42.27) JT3.15
  BOTTOM w0.381: v1(16.48,42.27) 14.56,40.36 14.56,33.14 15.83,31.87 15.83,26.28 17.23,24.89 19.64,24.89 20.07,24.45 RB14.2
RTD1: length 1
  TOP w0.635: RT27.2 v1(46.83,20.94)
RTD-ISO: length 44.4
  TOP w0.635: v1(47.4,14.85) 48.4,14.85 CT24.2
  LAYER3 w0.635: v1(47.4,14.85) 46.19,13.64 46.19,10.15 44.79,8.76 44.79,1.21 44.15,0.57 26.69,0.57 22.29,4.97 22.29,6.35 v1(22.91,6.97)
  BOTTOM w0.508: UB8.4 22.39,7.5 v1(22.91,6.97)
RTD-NON-ISO: length 13.5
  LAYER5 w0.508: v1(20.91,26.46) 20.91,17.01 v1(21.8,16.12)
  BOTTOM w0.305: v1(20.91,26.46) 20.91,27.03 UB6.9
  BOTTOM w0.381: v1(21.8,16.12) 22.39,16.71 UB8.13
RTD-OUTPUT-N: length 26.4
  TOP w0.254: JT3.10 25.23,38 24.58,38.65 v1(24.58,39.98)
  LAYER5 w0.254: v1(24.58,39.98) 17.69,39.98 17.56,39.84 16.98,39.84 v1(16.31,39.17)
  BOTTOM w0.254: UB6.11 19.37,28.48 19.3,28.41 18.61,28.41 17.89,29.14 17.89,31.93 16.05,33.77 16.05,38.92 v1(16.31,39.17)
RTD-OUTPUT-P: length 32.6
  TOP w0.254: v1(27.01,40.02) 26.52,40.51 26.52,42.99 26.11,43.4 JT3.9
  LAYER5 w0.254: v1(16.31,40.51) 16.35,40.51 17.07,41.23 17.65,41.23 18.25,40.63 24.82,40.63 25.43,40.02 v1(27.01,40.02)
  BOTTOM w0.254: v1(16.31,40.51) 15.55,39.75 15.55,33.55 17.38,31.72 17.38,28.93 18.4,27.9 19.3,27.9 19.37,27.83 UB6.10
UNPROTECTED_VIN:
  vias: v1(35.24,47.29) v1(35.88,46.02) v1(36.51,44.75) v1(37.15,46.02) v1(37.15,43.48) v1(37.78,44.75) v1(38.42,46.02) v1(38.42,43.48)
VOUT_OFF_HS:
  vias: v1(5.69,66.76) v1(5.69,63.2) v1(6.58,67.65) v1(6.58,64.09) v1(7.47,68.54) v1(7.47,66.76) v1(7.47,63.2) v1(15.4,69.72) v1(16.29,69.72) v1(17.18,69.72) v1(18.07,69.72) v1(18.96,69.72) v1(19.85,69.72) v1(20.74,69.72) v1(21.62,69.72) v1(22.51,69.72)
VOUT_OFF_LS:
  vias: v1(0.88,12.02) v1(0.88,10.24) v1(1.77,16.46) v1(1.77,12.91) v1(1.77,11.13) v1(2.66,15.58) v1(2.66,12.02) v1(2.66,10.24) v1(3.55,16.46) v1(3.55,11.13) v1(4.44,10.24) v1(21.04,7.02)
VOUT_ON_HS:
  vias: v1(0.8,68.6) v1(0.8,66.82) v1(0.8,63.26) v1(1.69,69.49) v1(1.69,67.71) v1(1.69,64.15) v1(2.58,68.6) v1(2.58,66.82) v1(2.58,63.26) v1(3.47,69.49) v1(3.47,67.71) v1(3.47,64.15) v1(19.9,72.98)
VOUT_ON_LS:
  vias: v1(5.6,16.47) v1(5.6,12.91) v1(6.49,15.58) v1(6.49,12.02) v1(7.38,16.47) v1(7.38,12.91) v1(7.38,11.13) v1(23.71,10.28)
N5110224: length 16
  TOP w0.381: RT34.1 RT33.1 CT27.1 v1(20.78,4.1) 19.91,4.97 DT11.C DT10.C
  TOP w0.508: v1(18.98,6.98) 18.88,7.08 18.88,8.28 UT7.10
  LAYER3 w0.508: v1(20.78,4.1) 18.98,5.9 v1(18.98,6.98)
N5110410: length 4
  TOP w0.381: 24.93,17.76 UT7.2 24.93,19.54 ; 24.93,19.54 25.64,20.26 RT26.2 ; 24.93,19.54 24.91,19.54 CT21.1
N5776744: length 3.4
  BOTTOM w0.254: RB5.2 29.84,42.57 30.95,41.46 30.95,40.76 31.2,40.51 UB4.4
N5776884: length 3.4
  BOTTOM w0.254: UB4.2 31.22,39.51 30.95,39.24 30.95,38.49 29.84,37.38 CB18.1
N5776892: length 11.2
  BOTTOM w0.381: UB5.1 26.25,38.03 25.43,37.22 21.7,37.22 CB17.1
  BOTTOM w0.508: RB6.1 RB8.1 RB9.2 CB17.1
N5776900: length 3.9
  BOTTOM w0.254: 29.84,39.11 30.04,39.11 30.93,40.01 ; 30.93,40.01 30.08,40.87 RB7.1 ; 30.93,40.01 UB4.3
N5786131: length 6.3
  BOTTOM w0.305: UB6.2 28.25,31.08 RB10.2
  BOTTOM w0.508: LB2.2 32.39,30.58 CB22.1 30.54,30.63 RB10.2
N5786223: length 6.3
  BOTTOM w0.305: UB6.1 28.21,31.73 RB10.1
  BOTTOM w0.508: LB1.2 CB22.2 30.54,32.23 RB10.1
N5786329: length 6.1
  BOTTOM w0.305: UB6.6 28.69,28.48 RB11.2
  BOTTOM w0.508: RB11.2 28.75,28.52 CB23.1 32.39,28.52 LB3.2
N5786365: length 6.5
  BOTTOM w0.305: UB6.7 27.69,27.83 28.65,26.87 RB11.1
  BOTTOM w0.508: LB4.2 CB23.2 28.75,26.92 RB11.1
N5786573: length 8.7
  BOTTOM w0.305: UB6.4 24.54,29.78 23.83,29.08 23.83,27.43 25.55,25.71 UB7.6
N5786769: length 6.3
  BOTTOM w0.381: UB7.1 26.08,21.93 CB24.1 RB13.1 29.35,21.93 30.95,23.53 RB12.1
N5791884: length 1.9
  TOP w0.381: DT8.1 9.27,35.44 RT19.1
N5791888: length 1.9
  TOP w0.381: RT13.1 9.27,44.56 DT6.1
N5813663: length 4.2
  TOP w0.381: UT3.1 19.83,55.62 v1(19.77,55.68) RT7.2
  BOTTOM w0.381: RT7.2 v1(19.77,55.68)
N5829702: length 7.2
  TOP w0.254: UT5.1 27,32.9 26.5,33.4 25.23,33.4 24.72,32.89 CT12.1
  TOP w0.381: RT20.2 CT12.1
N5829738: length 9.9
  TOP w0.254: v1(24.81,28.06) 25.27,28.06 UT5.5 25.5,29.09 26.5,30.09 UT5.2
  TOP w0.381: UT4.4 21.06,29.81 21.26,30.01 v1(22.14,30.01)
  LAYER5 w0.381: v1(24.81,28.06) 24.09,28.06 v1(22.14,30.01)
N5829966: length 5.3
  TOP w0.254: CT15.1 23.75,26.66 25.23,26.66 26,27.43 UT5.6
  TOP w0.381: CT15.1 RT21.2
N5871306: length 4.3
  TOP w0.381: RT10.2 v1(19.77,52.18) 20.13,51.81 UT3.4
  BOTTOM w0.381: RT10.2 v1(19.77,52.18)
N5941912: length 4.4
  TOP w0.381: RT8.2 v1(19.77,53.93) 20.19,54.35 UT3.2
  BOTTOM w0.381: RT8.2 v1(19.77,53.93)
N5941952: length 4.2
  TOP w0.381: UT3.5 19.89,50.54 v1(19.77,50.42) RT11.2
  BOTTOM w0.381: RT11.2 v1(19.77,50.42)
N5948959: length 6.7
  BOTTOM w0.305: UB1.6 38.4,72.18 RB2.2
  BOTTOM w0.508: CB7.2 RB2.2 RB3.2 RB4.2
N5949233: length 6.7
  BOTTOM w0.305: UB9.6 31.74,7.82 RB18.2
  BOTTOM w0.508: CB29.2 RB18.2 RB17.2 RB16.2
N6007380: length 2.5
  TOP w0.254: RT16.1 1.47,38.96 3.16,37.28 DT7.1
N6007384: length 2.5
  TOP w0.254: DT5.1 3.16,42.72 1.47,41.04 RT15.1
N6009828: length 15.9
  TOP w0.381: RT33.2 v1(24.78,0.95) ; v1(13.05,5.1) DT9.C
  LAYER3 w0.381: v1(13.05,5.1) 16.38,1.77 23.96,1.77 v1(24.78,0.95)
N6009832: length 38.6
  TOP w0.635: v1(11.26,1.5) DT9.A
  BOTTOM w0.635: 3.13,31.74 2.75,31.74 0.72,29.71 0.72,16 11.26,5.46 v1(11.26,1.5)
N6024502: length 7.7
  BOTTOM w0.381: RB15.2 CB26.1 RB14.1 20.12,21.93 20.99,21.06 23.31,21.06 UB7.3
N6026359: length 3.9
  TOP w0.381: 18.58,60.46 17.86,59.74 RT5.2 ; 18.58,60.46 18.59,60.46 CT5.1 ; 18.58,60.46 UT2.2
N6026535: length 4.1
  TOP w0.381: UT2.6 23.66,59.97 CT8.1 RT6.2
N6026555: length 15.2
  TOP w0.508: RT1.1 RT2.1 CT1.1 18.91,75.9 19.78,75.03 DT1.C DT2.C 23.09,74.9 24.93,73.07 UT2.10
N6026735: length 16.1
  TOP w0.508: v1(26.64,74.9) DT3.C ; RT2.2 v1(14.91,78.61)
  LAYER3 w0.508: v1(26.64,74.9) 26.64,76.31 24.34,78.61 v1(14.91,78.61)
N6026739: length 31.9
  TOP w0.508: v1(27.01,77.97) 26.48,78.5 DT3.A
  LAYER3 w0.508: v1(45.8,69.72) 42.5,73.02 42.5,78.73 41.87,79.37 28.41,79.37 v1(27.01,77.97)
  BOTTOM w0.635: v1(45.8,69.72) 48.74,69.72 DB1.A
N6026743:
  vias: v1(46.19,64.7) v1(46.19,62.16) v1(46.82,63.43) v1(51.65,63.43) v1(52.28,64.7) v1(52.28,62.16)
N6032095: length 4.1
  TOP w0.381: RT25.2 CT18.1 19.85,20.03 UT7.6
N57768605: length 2.1
  BOTTOM w0.381: UB5.6 27.98,41.12 RB7.2

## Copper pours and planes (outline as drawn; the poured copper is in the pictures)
5V on TOP: 40.97,40.89 40.79,40.96 40.71,41.14 40.71,45.42 40.79,45.6 40.97,45.67 45.41,45.67 45.59,45.6 45.66,45.42 45.66,41.14 45.59,40.96 45.41,40.89
5V on TOP: 0.51,34.33 0.33,34.4 0.25,34.58 0.25,35.73 0.33,35.91 0.51,35.98 4.35,35.98 4.41,36.04 9.88,36.04 9.88,38.03 13.95,38.03 14.13,38.11 14.2,38.29 14.2,41.71 14.13,41.89 13.95,41.97 9.88,41.97 9.88,43.96 4.5,43.96 4.44,44.02 0.51,44.02 0.33,44.09 0.25,44.27 0.25,45.42 0.33,45.6 0.51,45.67 14.94,45.67 15.12,45.6 15.2,45.42 15.2,34.58 15.12,34.4 14.94,34.33
5V on BOTTOM: 45,45.67 45.18,45.6 45.25,45.42 45.25,41.14 45.18,40.96 45,40.89 40.97,40.89 40.79,40.96 40.71,41.14 40.71,45.42 40.79,45.6 40.97,45.67
5V on LAYER4: 0.25,77.46 0.92,79.08 2.54,79.75 50.46,79.75 52.08,79.08 52.75,77.46 52.75,2.54 52.08,0.92 50.46,0.25 2.54,0.25 0.92,0.92 0.25,2.54
12V on TOP: 45.41,40.63 45.59,40.56 45.66,40.38 45.66,34.58 45.59,34.4 45.41,34.33 40.97,34.33 40.79,34.4 40.71,34.58 40.71,40.38 40.79,40.56 40.97,40.63
12V on BOTTOM: 45,39.11 45.18,39.04 45.25,38.86 45.25,34.58 45.18,34.4 45,34.33 40.97,34.33 40.79,34.4 40.71,34.58 40.71,38.86 40.79,39.04 40.97,39.11
12V on BOTTOM: 29.98,44.11 29.85,44.31 29.8,44.54 29.8,48 29.88,48.18 30.06,48.25 33.45,48.25 33.63,48.18 33.7,48 33.7,46.36 33.75,46.12 33.88,45.93 34.86,44.95 34.99,44.75 35.03,44.52 35.03,42.67 34.99,42.43 34.86,42.23 34.36,41.74 34.23,41.54 34.18,41.31 34.18,38.35 34.11,38.17 33.93,38.1 32.79,38.1 32.61,38.17 32.53,38.35 32.53,41.3 32.49,41.54 32.35,41.74
12V_SWITCHED on TOP: 31.96,50.35 31.78,50.27 31.71,50.09 31.71,47.24 31.75,47 31.89,46.81 32.95,45.74 33.15,45.6 33.39,45.56 33.6,45.56 33.6,40.76 33.68,40.58 33.86,40.51 36.41,40.51 36.59,40.58 36.66,40.76 36.66,41.02 36.59,41.2 36.41,41.28 34.64,41.28 34.64,50.09 34.56,50.27 34.38,50.35
12V_SWITCHED on BOTTOM: 36.34,41.28 36.52,41.2 36.59,41.02 36.59,37.49 36.67,37.41 36.8,37.21 36.85,36.98 36.85,34.06 36.92,33.88 37.1,33.81 43.46,33.81 41.21,31.81 40.37,28.92 36.02,28.92 35.85,28.99 35.77,29.17 35.77,33.27 35.72,33.5 35.59,33.7 34.3,34.99 34.17,35.19 34.12,35.43 34.12,37.53 34.26,37.67 34.39,37.87 34.44,38.1 34.44,41.02 34.51,41.2 34.69,41.28
-5V_HS on TOP: 34.12,69.56 34.05,69.38 33.87,69.31 27.77,69.31 27.59,69.38 27.52,69.56 27.52,71.34 27.59,71.52 27.77,71.59 33.87,71.59 34.05,71.52 34.12,71.34
-5V_HS on BOTTOM: 33.87,69.56 33.79,69.38 33.61,69.31 27.77,69.31 27.59,69.38 27.52,69.56 27.52,71.34 27.59,71.52 27.77,71.59 33.61,71.59 33.79,71.52 33.87,71.34
-5V_HS on BOTTOM: 39.48,74.16 39.48,75.94 38.55,75.94 38.55,76.77 38.11,76.77 37.93,76.84 37.86,77.02 37.86,78.73 37.78,78.91 37.6,78.98 34.69,78.98 34.51,78.91 34.44,78.73 34.44,75.56 34.51,75.38 34.69,75.31 36.82,75.31 36.82,74.16
-5V_HS on LAYER3: 27.77,71.49 27.84,71.67 28.02,71.74 34.25,71.74 34.43,71.82 34.5,72 34.5,78.6 34.58,78.78 34.76,78.86 39.33,78.86 39.51,78.78 39.58,78.6 39.58,69.56 39.51,69.38 39.33,69.31 28.02,69.31 27.84,69.38 27.77,69.56
-5V_LS on TOP: 43.01,10.69 43.19,10.62 43.26,10.44 43.26,8.66 43.19,8.48 43.01,8.41 36.28,8.41 36.1,8.33 36.02,8.15 36.02,1.26 35.95,1.09 35.77,1.01 29.42,1.01 29.42,9.47 29.5,9.65 29.68,9.72 32.67,9.72 32.91,9.77 33.11,9.9 33.72,10.51 33.92,10.65 34.15,10.69
-5V_LS on BOTTOM: 36.91,10.44 36.99,10.62 37.17,10.69 43.01,10.69 43.19,10.62 43.26,10.44 43.26,8.66 43.19,8.48 43.01,8.41 37.17,8.41 36.99,8.48 36.91,8.66
-5V_LS on BOTTOM: 30.66,5.84 30.66,4.06 31.59,4.06 31.59,3.23 32.03,3.23 32.21,3.16 32.29,2.98 32.29,1.27 32.36,1.09 32.54,1.02 35.45,1.02 35.63,1.09 35.71,1.27 35.71,4.44 35.63,4.62 35.45,4.69 33.58,4.69 33.4,4.77 33.33,4.95 33.33,5.84
0 on TOP: 23.19,38.5 23.19,34.7 17.11,34.7 17.11,38.5
0 on TOP: 45.93,45.42 46.01,45.6 46.19,45.67 52.49,45.67 52.67,45.6 52.75,45.42 52.75,34.58 52.67,34.4 52.49,34.33 46.19,34.33 46.01,34.4 45.93,34.58
0 on TOP: 30.57,25.52 30.39,25.45 30.32,25.27 30.32,24 30.39,23.82 30.57,23.74 33.36,23.74 33.54,23.82 33.61,24 33.61,25.27 33.54,25.45 33.36,25.52
0 on TOP: 13.42,38.73 13.18,38.78 12.99,38.91 12.31,39.59 12.11,39.72 11.87,39.77 1.83,39.77 1.83,36.24 0.51,36.24 0.33,36.31 0.25,36.49 0.25,43.51 0.33,43.69 0.51,43.76 1.83,43.76 1.83,40.23 11.89,40.23 12.13,40.28 12.33,40.41 13.01,41.09 13.21,41.22 13.44,41.27 13.95,41.27 13.95,38.73
0 on TOP: 40.42,54.48 40.6,54.55 40.67,54.73 40.67,56 40.6,56.18 40.42,56.26 37.42,56.26 37.24,56.18 37.17,56 37.17,54.73 37.24,54.55 37.42,54.48
0 on BOTTOM: 45.51,45.42 45.58,45.6 45.76,45.67 52.49,45.67 52.67,45.6 52.75,45.42 52.75,34.58 52.67,34.4 52.49,34.33 45.76,34.33 45.58,34.4 45.51,34.58
0 on BOTTOM: 37.35,34.06 37.17,34.13 37.1,34.31 37.1,36.32 37.17,36.5 37.35,36.57 38.52,36.57 38.7,36.5 38.78,36.32 38.78,34.31 38.7,34.13 38.52,34.06
0 on BOTTOM: 32.6,34.03 32.52,33.85 32.34,33.78 27.26,33.78 27.08,33.85 27.01,34.03 27.01,39.62 27.08,39.8 27.26,39.87 28.53,39.87 28.71,39.8 28.79,39.62 28.79,36.6 29.6,36.6 31.36,38.36 31.36,39.15 32.28,39.15 32.28,38.1 32.33,37.87 32.46,37.67 32.6,37.53
0 on LAYER2, LAYER5: 0.25,77.46 0.92,79.08 2.54,79.75 50.46,79.75 52.08,79.08 52.75,77.46 52.75,2.54 52.08,0.92 50.46,0.25 2.54,0.25 0.92,0.92 0.25,2.54
0 on LAYER4: 52.49,45.67 52.67,45.6 52.75,45.42 52.75,34.58 52.67,34.4 52.49,34.33 46.19,34.33 46.01,34.4 45.93,34.58 45.93,45.42 46.01,45.6 46.19,45.67
HS-DRAIN on TOP, LAYER2, LAYER3, LAYER4, LAYER5: 52.11,59.18 52.56,58.99 52.75,58.54 52.75,51.38 52.56,50.94 52.11,50.75 46.39,50.75 45.94,50.94 45.75,51.38 45.75,58.54 45.94,58.99 46.39,59.18
HS-GATE on TOP: 8.21,50.75 8.66,50.94 8.85,51.38 8.85,62.04 8.77,62.22 8.59,62.3 0.51,62.3 0.33,62.22 0.25,62.04 0.25,51.38 0.44,50.94 0.89,50.75
HS-SOURCE on TOP: 34.12,73.91 34.05,74.09 33.87,74.16 30.06,74.16 29.88,74.24 29.8,74.42 29.8,75.81 29.73,75.99 29.55,76.07 27.77,76.07 27.59,75.99 27.52,75.81 27.52,72.15 27.59,71.97 27.77,71.9 33.87,71.9 34.05,71.97 34.12,72.15
HS-SOURCE on BOTTOM: 19.52,77.72 19.59,77.9 19.77,77.97 22.56,77.97 22.74,77.9 22.82,77.72 22.82,73.65 22.89,73.48 23.07,73.4 27.26,73.4 27.44,73.48 27.52,73.65 27.52,73.91 27.59,74.09 27.77,74.16 35.23,74.16 35.41,74.09 35.48,73.91 35.48,71.37 35.56,71.19 35.74,71.11 35.93,71.11 35.93,69.56 35.85,69.38 35.67,69.31 34.37,69.31 34.19,69.38 34.12,69.56 34.12,71.64 34.05,71.82 33.87,71.9 27.52,71.9 27.34,71.82 27.26,71.64 27.26,69.56 27.19,69.38 27.01,69.31 23.32,69.31 23.15,69.38 23.07,69.56 23.07,72.26 23,72.44 22.82,72.51 19.77,72.51 19.59,72.59 19.52,72.77
HS-VDD on TOP: 33.87,74.42 34.05,74.49 34.12,74.67 34.12,78.73 34.05,78.91 33.87,78.99 27.77,78.99 27.59,78.91 27.52,78.73 27.52,76.82 27.59,76.65 27.77,76.57 29.8,76.57 29.98,76.5 30.06,76.32 30.06,74.67 30.13,74.49 30.31,74.42
HS-VSS on BOTTOM: 39.77,74.63 39.84,74.8 40.02,74.88 42.25,74.88 42.43,74.8 42.5,74.63 42.5,69.56 42.43,69.38 42.25,69.31 36.44,69.31 36.26,69.38 36.18,69.56 36.18,72.75 34.72,72.75 34.54,72.82 34.47,73 34.47,74.63 34.54,74.8 34.72,74.88 36.34,74.88 36.52,74.8 36.59,74.63 36.59,73.92 39.77,73.92
HS-VSS on BOTTOM: 23.33,77.97 23.15,77.9 23.07,77.72 23.07,73.91 23.15,73.73 23.33,73.65 27.01,73.65 27.19,73.73 27.26,73.91 27.26,77.72 27.19,77.9 27.01,77.97
LS-GATE on TOP: 0.89,29.25 0.44,29.06 0.25,28.62 0.25,17.58 0.33,17.4 0.51,17.32 8.59,17.32 8.77,17.4 8.85,17.58 8.85,28.62 8.66,29.06 8.21,29.25
LS-SOURCE on TOP: 36.02,6.09 36.1,5.91 36.28,5.84 40.72,5.84 40.9,5.76 40.98,5.58 40.98,4.19 41.05,4.01 41.23,3.93 43.01,3.93 43.19,4.01 43.26,4.19 43.26,7.9 43.19,8.08 43.01,8.15 36.28,8.15 36.1,8.08 36.02,7.9
LS-SOURCE on BOTTOM: 30.41,3.87 31.4,3.87 31.4,2.98 31.45,2.98 31.63,2.9 31.71,2.72 31.71,1.27 31.63,1.09 31.45,1.02 27.9,1.02 27.72,1.09 27.64,1.27 27.64,3.87 27.57,4.05 27.39,4.12 25.91,4.12 25.68,4.17 25.48,4.3 23.7,6.07 23.7,7.1 24.65,7.1 24.65,6.1 25.75,5 25.95,4.87 26.18,4.82 30.15,4.82 30.33,4.75 30.41,4.57
LS-SOURCE on BOTTOM: 16.09,7.33 20.91,7.33 20.91,0.25 16.09,0.25
LS-SOURCE on LAYER2: 0.25,28.62 0.44,29.06 0.89,29.25 8.21,29.25 8.66,29.06 8.85,28.62 8.85,10.69 45.45,10.69 45.45,19.3 47.2,19.3 47.38,19.37 47.45,19.55 47.45,21.08 47.53,21.26 47.71,21.33 52.75,21.33 52.75,2.54 52.08,0.92 50.46,0.25 2.54,0.25 0.92,0.92 0.25,2.54 ; 3 cut-outs
LS-VDD on TOP: 22.69,9.59 22.06,9.59 21.88,9.51 21.8,9.33 21.8,6.73 21.04,5.96 21.04,4.82 21.11,4.64 21.29,4.57 21.8,4.57 22.06,4.83 23.83,4.83 24.01,4.9 24.09,5.08 24.09,5.93 24.04,6.16 23.91,6.36 22.69,7.58
LS-VDD on TOP: 36.91,5.46 36.73,5.39 36.66,5.21 36.66,1.26 36.73,1.09 36.91,1.01 43.01,1.01 43.19,1.09 43.26,1.26 43.26,3.18 43.19,3.35 43.01,3.43 40.98,3.43 40.8,3.5 40.72,3.68 40.72,5.21 40.65,5.39 40.47,5.46
LS-VDD on BOTTOM: 20.91,6.47 22.95,6.47 25.37,4.05 25.57,3.91 25.8,3.87 27.13,3.87 27.31,3.79 27.39,3.61 27.39,1.02 27.46,0.84 27.64,0.76 35.71,0.76 35.89,0.84 35.96,1.02 35.96,5.33 36.04,5.51 36.22,5.58 40.47,5.58 40.65,5.51 40.72,5.33 40.72,3.68 40.8,3.5 40.98,3.43 43.01,3.43 43.19,3.35 43.26,3.18 43.26,0.51 43.19,0.33 43.01,0.25 20.91,0.25
LS-VSS on BOTTOM: 16.09,0.25 11.89,0.25 11.89,7.33 16.09,7.33
RTD1 on LAYER2: 45.45,28.62 45.64,29.06 46.09,29.25 52.11,29.25 52.56,29.06 52.75,28.62 52.75,21.59 47.45,21.59 47.28,21.51 47.2,21.33 47.2,19.81 47.13,19.63 46.95,19.55 45.45,19.55
RTD2 on TOP: 45.45,28.62 45.64,29.06 46.09,29.25 52.11,29.25 52.56,29.06 52.75,28.62 52.75,22.04 52.7,21.81 52.57,21.61 50.82,19.86 50.62,19.73 50.38,19.68 49.74,19.68 49.56,19.75 49.49,19.93 49.49,22.81 49.41,22.99 49.23,23.06 45.7,23.06 45.52,23.14 45.45,23.32
RTD-ISO on TOP: 48.75,18.59 48.88,18.39 48.93,18.16 48.93,14.52 48.85,14.34 48.67,14.26 48.03,14.26 47.85,14.34 47.77,14.52 47.77,16.95 47.7,17.13 47.52,17.21 45.7,17.21 45.52,17.28 45.45,17.46 45.45,18.79 45.52,18.97 45.7,19.04 48.04,19.04 48.27,19 48.47,18.87
UNPROTECTED_VIN on BOTTOM: 34.21,48.25 34.03,48.18 33.95,48 33.95,46.46 34,46.23 34.13,46.03 35.11,45.06 35.24,44.86 35.29,44.62 35.29,43.17 35.36,43 35.54,42.92 38.78,42.92 38.96,43 39.03,43.17 39.03,48 38.96,48.18 38.78,48.25
VOUT_OFF_HS on TOP: 5.13,62.55 4.95,62.62 4.88,62.8 4.88,67.02 4.92,67.25 5.06,67.45 8.79,71.19 8.99,71.32 9.23,71.37 21.67,71.37 21.67,72.26 21.75,72.44 21.93,72.51 22.82,72.51 23,72.44 23.07,72.26 23.07,69.56 23,69.38 22.82,69.31 8.85,69.31 8.85,62.8 8.77,62.62 8.59,62.55
VOUT_OFF_LS on TOP: 21.55,9.33 21.47,9.51 21.29,9.59 20.66,9.59 20.48,9.51 20.41,9.33 20.41,7.02 19.94,6.56 18.63,6.56 18.63,8.5 9.1,8.5 8.87,8.55 8.67,8.68 4.3,13.05 4.17,13.25 4.12,13.48 4.12,16.81 4.05,16.99 3.87,17.07 0.51,17.07 0.33,16.99 0.25,16.81 0.25,9.46 0.33,9.28 0.51,9.21 4.21,9.21 7.09,8.28 8.9,5.85 20.7,5.85 20.93,5.9 21.13,6.03 21.37,6.27 21.5,6.47 21.55,6.7
VOUT_OFF_LS on LAYER3: 8.47,9.14 8.23,9.19 8.03,9.32 4.3,13.05 4.17,13.25 4.12,13.48 4.12,16.81 4.05,16.99 3.87,17.07 0.51,17.07 0.33,16.99 0.25,16.81 0.25,9.46 0.33,9.28 0.51,9.21 4.21,9.21 7.09,8.28 8.9,5.85 20.7,5.85 20.93,5.9 21.13,6.03 21.37,6.27 21.5,6.47 21.55,6.7 21.55,8.88 21.47,9.06 21.29,9.14
VOUT_ON_HS on TOP: 0.51,62.55 0.33,62.62 0.25,62.8 0.25,70.54 0.33,70.72 0.51,70.8 4.13,70.8 7.08,71.74 8.93,74.22 15.12,74.22 15.56,74.67 18.35,74.67 18.67,74.35 20.53,74.35 20.53,70.67 20.46,70.49 20.28,70.41 19.39,70.41 19.21,70.49 19.13,70.67 19.13,71.62 9.1,71.62 8.87,71.58 8.67,71.44 4.3,67.08 4.17,66.88 4.12,66.65 4.12,62.8 4.05,62.62 3.87,62.55
VOUT_ON_LS on TOP, BOTTOM: 22.94,9.59 22.87,9.77 22.69,9.84 17.55,9.84 16.47,8.76 9.21,8.76 8.97,8.8 8.77,8.94 5.06,12.65 4.92,12.85 4.88,13.09 4.88,16.81 4.95,16.99 5.13,17.07 8.59,17.07 8.77,16.99 8.85,16.81 8.85,10.69 24.09,10.69 24.27,10.62 24.34,10.44 24.34,7.83 24.27,7.65 24.09,7.58 23.2,7.58 23.02,7.65 22.94,7.83
N5143626 on TOP: 40.67,47.04 40.6,46.86 40.42,46.79 36.91,46.79 36.73,46.86 36.66,47.04 36.66,50.07 36.71,50.3 36.84,50.5 37.62,51.28 37.75,51.48 37.8,51.71 37.8,53.61 37.87,53.79 38.05,53.86 40.42,53.86 40.6,53.79 40.67,53.61
N5777665 on TOP: 30.41,52.09 30.48,51.91 30.66,51.83 34.37,51.83 34.55,51.91 34.63,52.09 34.63,61.23 34.55,61.41 34.37,61.48 31.94,61.48 31.76,61.41 31.68,61.23 31.68,59.4 31.73,59.17 31.86,58.97 32.8,58.02 32.94,57.83 32.98,57.59 32.98,54.22 32.91,54.04 32.73,53.97 30.66,53.97 30.48,53.9 30.41,53.72
N5777665 on BOTTOM: 37.55,59.3 37.47,59.12 37.3,59.04 31.83,59.04 31.65,59.12 31.58,59.3 31.58,61.2 31.65,61.38 31.83,61.46 37.3,61.46 37.47,61.38 37.55,61.2
N5777737 on TOP: 32.48,54.22 32.65,54.3 32.73,54.48 32.73,57.49 32.68,57.72 32.55,57.92 31.61,58.86 31.47,59.06 31.43,59.3 31.43,61.43 31.5,61.61 31.68,61.69 34.37,61.69 34.55,61.76 34.63,61.94 34.63,63.97 34.55,64.15 34.37,64.23 30.66,64.23 30.48,64.15 30.41,63.97 30.41,54.48 30.48,54.3 30.66,54.22
N5777737 on BOTTOM: 37.55,61.97 37.47,61.79 37.3,61.71 31.83,61.71 31.65,61.79 31.58,61.97 31.58,63.87 31.65,64.05 31.83,64.12 37.3,64.12 37.47,64.05 37.55,63.87
